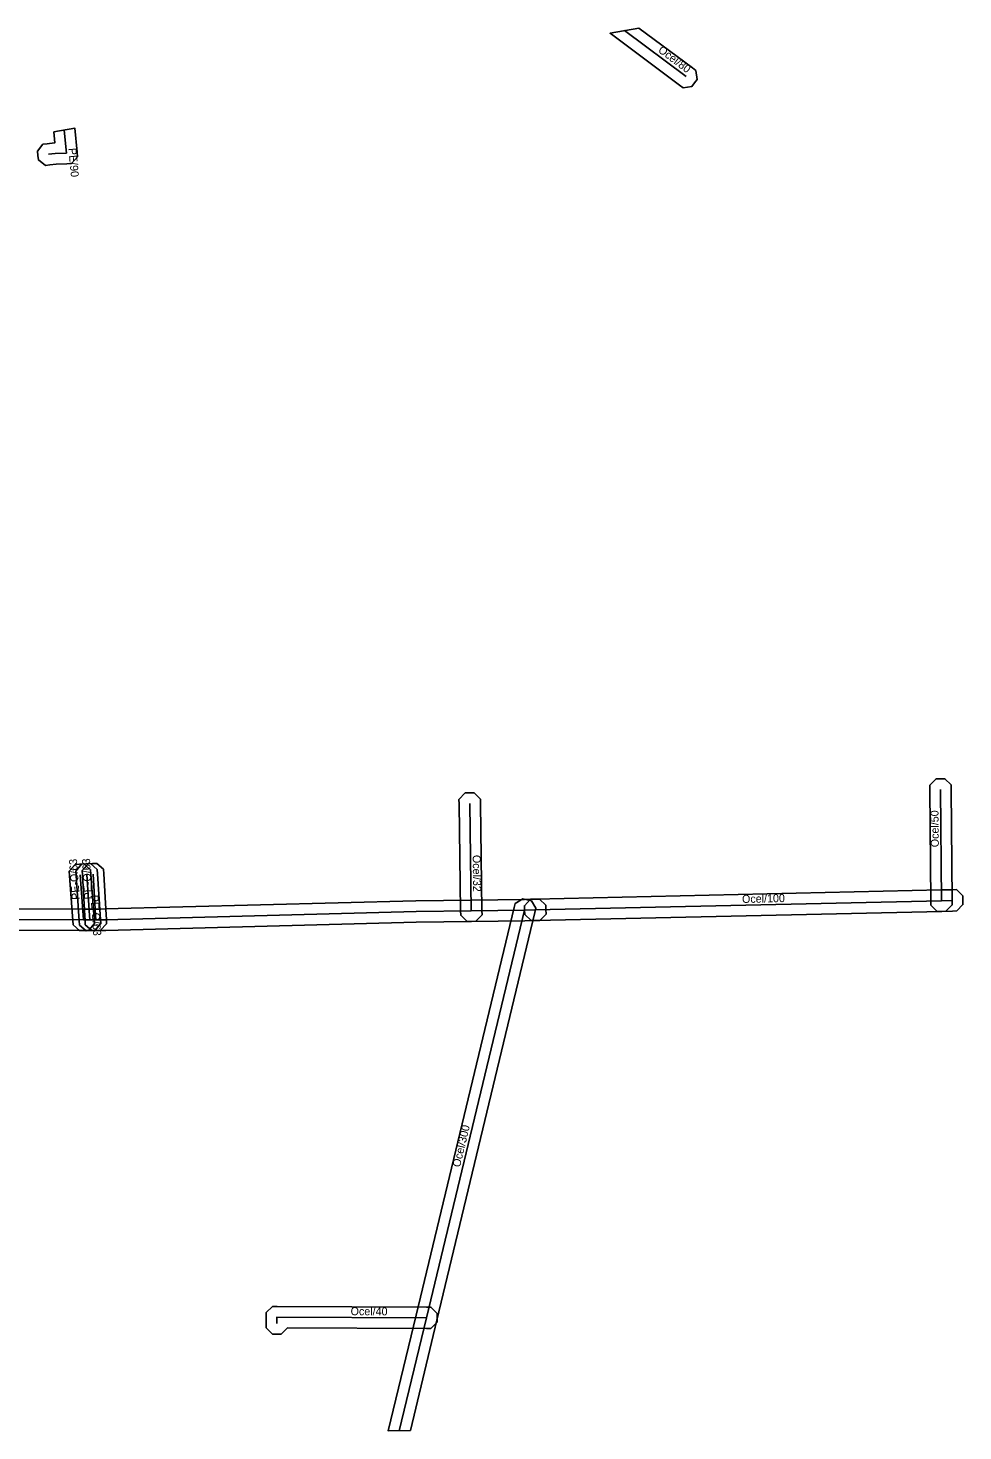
# Model space of a CAD drawing. Extents: x -702844 to -702342, y -1011731 to -1011542.
# Drawn here: x -702429.5 to -702342, y -1011720.4 to -1011589 of the extents above; entities that cross this region are included whole.
import ezdxf

# ---------------------------------------------------------------- set-up
doc = ezdxf.new("R2010")
doc.units = 0
for name, color, linetype in [('1', 7, 'Continuous'), ('14', 7, 'Continuous'), ('18', 7, 'Continuous'), ('20', 7, 'Continuous'), ('24', 7, 'Continuous'), ('30', 7, 'Continuous')]:
    doc.layers.add(name, color=color, linetype=linetype)

msp = doc.modelspace()

# ---------------------------------------------------------------- linework, layer by layer
at = {"layer": '1'}
for points in [[(-702368.5, -1011594.33), (-702375.01, -1011589.47), (-702372.31, -1011588.99), (-702367.3, -1011592.73), (-702366.97, -1011592.98), (-702366.85, -1011593.8), (-702367.1, -1011594.13), (-702367.35, -1011594.46), (-702368.17, -1011594.58)], [(-702427.11, -1011598.72), (-702425.13, -1011598.37), (-702424.92, -1011600.62), (-702424.89, -1011601.05), (-702425.17, -1011601.37), (-702425.45, -1011601.69), (-702425.88, -1011601.71), (-702426.88, -1011601.75), (-702427.48, -1011601.82), (-702427.89, -1011601.86), (-702428.54, -1011601.35), (-702428.59, -1011600.94), (-702428.64, -1011600.53), (-702428.12, -1011599.88), (-702427.71, -1011599.83), (-702427.04, -1011599.75), (-702427.01, -1011599.75)], [(-702344.98, -1011671.17), (-702344.98, -1011670.76), (-702345.07, -1011660.33), (-702345.07, -1011659.92), (-702344.49, -1011659.33), (-702344.08, -1011659.33), (-702343.66, -1011659.32), (-702343.07, -1011659.9), (-702343.07, -1011660.32), (-702342.98, -1011670.74), (-702342.98, -1011671.15), (-702343.56, -1011671.74), (-702343.97, -1011671.75), (-702344.39, -1011671.75)], [(-702387.16, -1011661.23), (-702387.15, -1011661.64), (-702387.01, -1011671.68), (-702387, -1011672.09), (-702387.58, -1011672.68), (-702387.99, -1011672.69), (-702388.4, -1011672.7), (-702389, -1011672.12), (-702389.01, -1011671.71), (-702389.15, -1011661.67), (-702389.16, -1011661.26), (-702388.58, -1011660.66), (-702388.17, -1011660.66), (-702387.75, -1011660.65)], [(-702425.28, -1011673.02), (-702425.31, -1011672.61), (-702425.34, -1011672.19), (-702425.62, -1011668.41), (-702425.65, -1011668), (-702425.11, -1011667.37), (-702424.69, -1011667.34), (-702424.28, -1011667.31), (-702423.65, -1011667.85), (-702423.62, -1011668.27), (-702423.34, -1011672.05), (-702423.31, -1011672.47), (-702423.28, -1011672.88), (-702423.83, -1011673.51), (-702424.24, -1011673.54), (-702424.65, -1011673.57)], [(-702423.05, -1011667.83), (-702423.02, -1011668.24), (-702422.75, -1011672.06), (-702422.72, -1011672.47), (-702422.69, -1011672.88), (-702423.23, -1011673.51), (-702423.65, -1011673.54), (-702424.06, -1011673.57), (-702424.69, -1011673.03), (-702424.72, -1011672.61), (-702424.75, -1011672.2), (-702425.02, -1011668.38), (-702425.05, -1011667.97), (-702424.5, -1011667.34), (-702424.09, -1011667.31), (-702423.68, -1011667.28)], [(-702424.16, -1011673), (-702424.18, -1011672.59), (-702424.2, -1011672.17), (-702424.42, -1011668.34), (-702424.44, -1011667.92), (-702423.89, -1011667.31), (-702423.48, -1011667.28), (-702423.06, -1011667.26), (-702422.45, -1011667.81), (-702422.42, -1011668.22), (-702422.2, -1011672.07), (-702422.18, -1011672.49), (-702422.16, -1011672.91), (-702422.72, -1011673.52), (-702423.13, -1011673.54), (-702423.55, -1011673.56)], [(-702391.24, -1011710.06), (-702393.71, -1011720.38), (-702395.78, -1011720.43), (-702393.18, -1011709.59), (-702383.99, -1011671.4), (-702383.89, -1011671), (-702383.19, -1011670.57), (-702382.78, -1011670.66), (-702382.38, -1011670.76), (-702381.95, -1011671.46), (-702382.05, -1011671.87)], [(-702382.45, -1011670.62), (-702382.04, -1011670.61), (-702344.01, -1011669.75), (-702343.01, -1011669.72), (-702342.59, -1011669.71), (-702341.99, -1011670.29), (-702341.98, -1011670.7), (-702341.97, -1011671.11), (-702342.55, -1011671.71), (-702342.96, -1011671.72), (-702343.96, -1011671.75), (-702381.99, -1011672.61), (-702382.41, -1011672.62), (-702383.01, -1011672.05), (-702383.02, -1011671.63), (-702383.03, -1011671.22)], [(-702392.21, -1011710.83), (-702405.21, -1011710.76), (-702405.21, -1011710.78), (-702405.8, -1011711.36), (-702406.22, -1011711.36), (-702406.63, -1011711.36), (-702407.21, -1011710.77), (-702407.21, -1011710.35), (-702407.21, -1011709.75), (-702407.21, -1011709.34), (-702406.62, -1011708.76), (-702406.2, -1011708.76), (-702392.2, -1011708.83), (-702391.79, -1011708.83), (-702391.21, -1011709.42), (-702391.21, -1011709.83), (-702391.21, -1011710.25), (-702391.8, -1011710.83)]]:
    msp.add_lwpolyline(points, close=True, dxfattribs=at)
msp.add_lwpolyline([(-702454.54, -1011671.44), (-702424.31, -1011671.54), (-702423.72, -1011671.54), (-702423.16, -1011671.54), (-702422.94, -1011671.55), (-702422.69, -1011671.54), (-702422.3, -1011671.53), (-702393.19, -1011670.75), (-702388.02, -1011670.69), (-702383.04, -1011670.63), (-702382.04, -1011670.61), (-702381.63, -1011670.6), (-702381.03, -1011671.17), (-702381.02, -1011671.59), (-702381.01, -1011672), (-702381.58, -1011672.6), (-702381.99, -1011672.61), (-702383, -1011672.63), (-702387.99, -1011672.69), (-702393.16, -1011672.75), (-702422.24, -1011673.53), (-702422.64, -1011673.54), (-702422.95, -1011673.55), (-702423.2, -1011673.54), (-702423.72, -1011673.54), (-702424.31, -1011673.54), (-702454.53, -1011673.44)], dxfattribs=at)
at = {"layer": '14'}
for points in [[(-702388.15, -1011661.66), (-702388.01, -1011671.69)], [(-702424.31, -1011672.54), (-702424.34, -1011672.12), (-702424.62, -1011668.34)], [(-702424.02, -1011668.31), (-702423.75, -1011672.13), (-702423.72, -1011672.54)], [(-702423.18, -1011672.54), (-702423.2, -1011672.12), (-702423.42, -1011668.28)], [(-702382.02, -1011671.61), (-702383.02, -1011671.63), (-702388.01, -1011671.69), (-702393.17, -1011671.75), (-702422.27, -1011672.53), (-702422.66, -1011672.54), (-702422.95, -1011672.55), (-702423.18, -1011672.54), (-702423.72, -1011672.54), (-702424.31, -1011672.54), (-702454.54, -1011672.44), (-702490.61, -1011672.84), (-702537.22, -1011673.37)], [(-702394.75, -1011720.41), (-702392.21, -1011709.83), (-702383.02, -1011671.63)], [(-702382.02, -1011671.61), (-702343.98, -1011670.75), (-702342.98, -1011670.72)], [(-702392.21, -1011709.83), (-702406.21, -1011709.76), (-702406.21, -1011710.36)]]:
    msp.add_lwpolyline(points, dxfattribs=at)
at = {"layer": '18'}
for points in [[(-702373.66, -1011589.23), (-702367.9, -1011593.53)], [(-702343.98, -1011670.75), (-702344.07, -1011660.33)]]:
    msp.add_lwpolyline(points, dxfattribs=at)
at = {"layer": '24'}
msp.add_lwpolyline([(-702427.6, -1011600.82), (-702426.96, -1011600.75), (-702425.92, -1011600.71), (-702426.12, -1011598.55)], dxfattribs=at)

# ---------------------------------------------------------------- texts
at = {"layer": '20'}
for s, rotation, p in [('Ocel/80', 323.2249, (-702370.58, -1011591.18)), ('Ocel/50', 90.4673, (-702344.23, -1011665.74)), ('Ocel/32', 270.8336, (-702387.88, -1011666.47)), ('PE-O/63', 94.2364, (-702424.66, -1011670.64)), ('PE-O/63', 93.279, (-702423.5, -1011670.61)), ('PE-O/63', 274.043, (-702423.67, -1011670.23)), ('Ocel/100', 1.3013, (-702362.65, -1011670.97)), ('Ocel/300', 76.4714, (-702389.07, -1011695.77)), ('Ocel/40', 359.7135, (-702399.31, -1011709.59))]:
    msp.add_text(s, height=0.75, rotation=rotation, dxfattribs=at).set_placement(p)
at = {"layer": '30'}
msp.add_text('PE/90', height=0.75, rotation=275.2418, dxfattribs=at).set_placement((-702425.74, -1011600.26))

doc.saveas('drawing.dxf')
